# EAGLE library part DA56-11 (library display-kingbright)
14.22mm (0.56INCH) DUAL DIGIT NUMERIC DISPLAYS Source: www.kingbright.com .. DA56-11SRWA.pdf
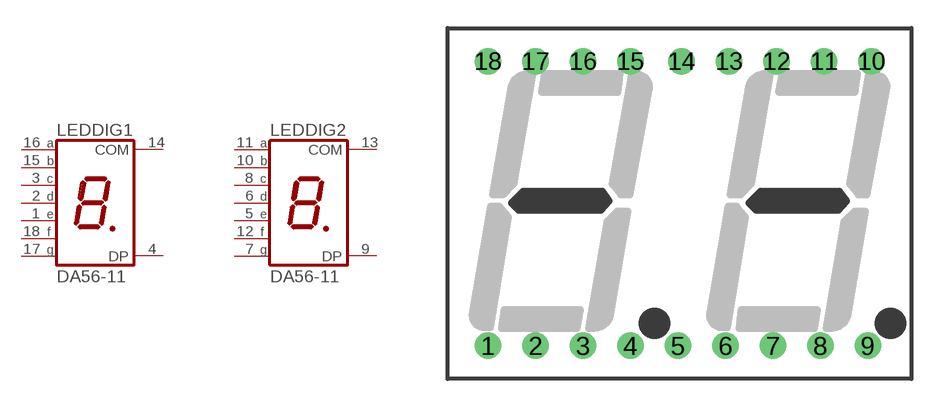
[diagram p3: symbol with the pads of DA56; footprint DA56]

Designator prefix LED; gates DIG1=7SEG-LED-COM1 DIG2=7SEG-LED-COM1

## DA56-11EWA (OC_FARNELL: unknown; OC_NEWARK: unknown), DA56-11GWA (OC_FARNELL: unknown; OC_NEWARK: unknown), DA56-11SRWA (OC_FARNELL: unknown; OC_NEWARK: unknown), DA56-11YWA (OC_FARNELL: unknown; OC_NEWARK: unknown)  [DA56]
1  DIG1:E  pas
2  DIG1:D  pas
3  DIG1:C  pas
4  DIG1:DP  pas
5  DIG2:E  pas
6  DIG2:D  pas
7  DIG2:G  pas
8  DIG2:C  pas
9  DIG2:DP  pas
10  DIG2:B  pas
11  DIG2:A  pas
12  DIG2:F  pas
13  DIG2:COM  pas
14  DIG1:COM  pas
15  DIG1:B  pas
16  DIG1:A  pas
17  DIG1:G  pas
18  DIG1:F  pas

## Footprint DA56 (pad centres in mm)
14.22mm (0.56INCH) DUAL DIGIT NUMERIC DISPLAYS Source: DA56-11SRWA.pdf
drill 0.8 pad 1.422 round: 1 -10.26,-7.62; 2 -7.72,-7.62; 3 -5.18,-7.62; 4 -2.64,-7.62; 5 -0.1,-7.62; 6 2.44,-7.62; 7 4.98,-7.62; 8 7.52,-7.62; 9 10.06,-7.62; 10 10.26,7.62; 11 7.72,7.62; 12 5.18,7.62; 13 2.64,7.62; 14 0.1,7.62; 15 -2.64,7.62; 16 -5.18,7.62; 17 -7.72,7.62; 18 -10.26,7.62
